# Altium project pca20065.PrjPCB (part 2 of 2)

## Sheet pca20065_switch_nx.SchDoc: =BoardTitle + ' - Switch NX'
size A3; Organization: Nordic Semiconductor; DocumentNumber: 10; Revision: 2.0.0; SheetNumber: 10; SheetTotal: 10; Author: GETR; CompanyName: Nordic Semiconductor; DrawnBy: GETR; DocumentSize: A4
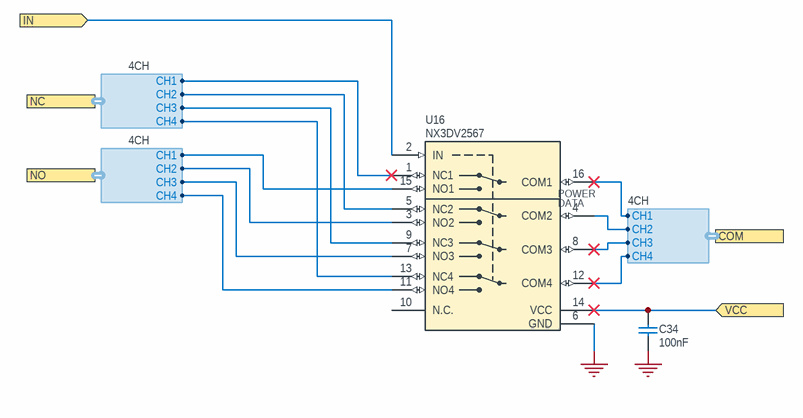
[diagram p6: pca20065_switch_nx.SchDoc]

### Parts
C34  100nF  [CAPC0603X03L_C]
U16  NX3DV2567  [XQFN40P180X260X50-16N]

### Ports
COM (harness 4CH), IN (in), NC (harness 4CH), NO (harness 4CH), VCC (in)

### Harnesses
4CH: CH1, CH2, CH3, CH4

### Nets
GND: C34.1 U16.6(GND)
4FF_1V8: U16.1(NC1) ; port NC.CH1
4FF_CLK: U16.9(NC3) ; port NC.CH3
4FF_DETECT: U16.2(IN) ; port IN
4FF_IO: U16.5(NC2) ; port NC.CH2
4FF_RST: U16.13(NC4) ; port NC.CH4
MFF_1V8: U16.15(NO1) ; port NO.CH1
MFF_CLK: U16.7(NO3) ; port NO.CH3
MFF_IO: U16.3(NO2) ; port NO.CH2
MFF_RST: U16.11(NO4) ; port NO.CH4
SIM.1V8: C34.2 U16.14(VCC) U16.16(COM1) ; port VCC, port COM.CH1
SIM.CLK: U16.8(COM3) ; port COM.CH3
SIM.IO: U16.4(COM2) ; port COM.CH2
SIM.RST: U16.12(COM4) ; port COM.CH4

Not connected (* = marked no-connect by the designer): U16 10(N.C.)

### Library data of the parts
C34 = C0201-100n: Capacitor, X5R, ±10%; Manufacturer: N.A.; Part number IPS: 00000001248, 00000002505; Part number Norautron: 262071862; Part number NEMS: 100200078; Note: 16V; Pad Count: 2; Component Status: Active
U16 = NX3DV2567GU: Low-ohmic four-pole double-throw analog switch; Manufacturer: NXP Semiconductors; Part number IPS: 00000007816; Part number NEMS: 101900290; Note: N.A.; Artikkelnr Noca: 15079317; Pad Count: 16; Component Status: Active

## Sheet pca20065_power_supply.SchDoc: =BoardTitle + ' - Power Supply'
size A3; Organization: Nordic Semiconductor; DocumentNumber: 7; Revision: 2.0.0; SheetNumber: 7; SheetTotal: 10; Author: GETR; CompanyName: Nordic Semiconductor; DrawnBy: GETR; DocumentSize: A3
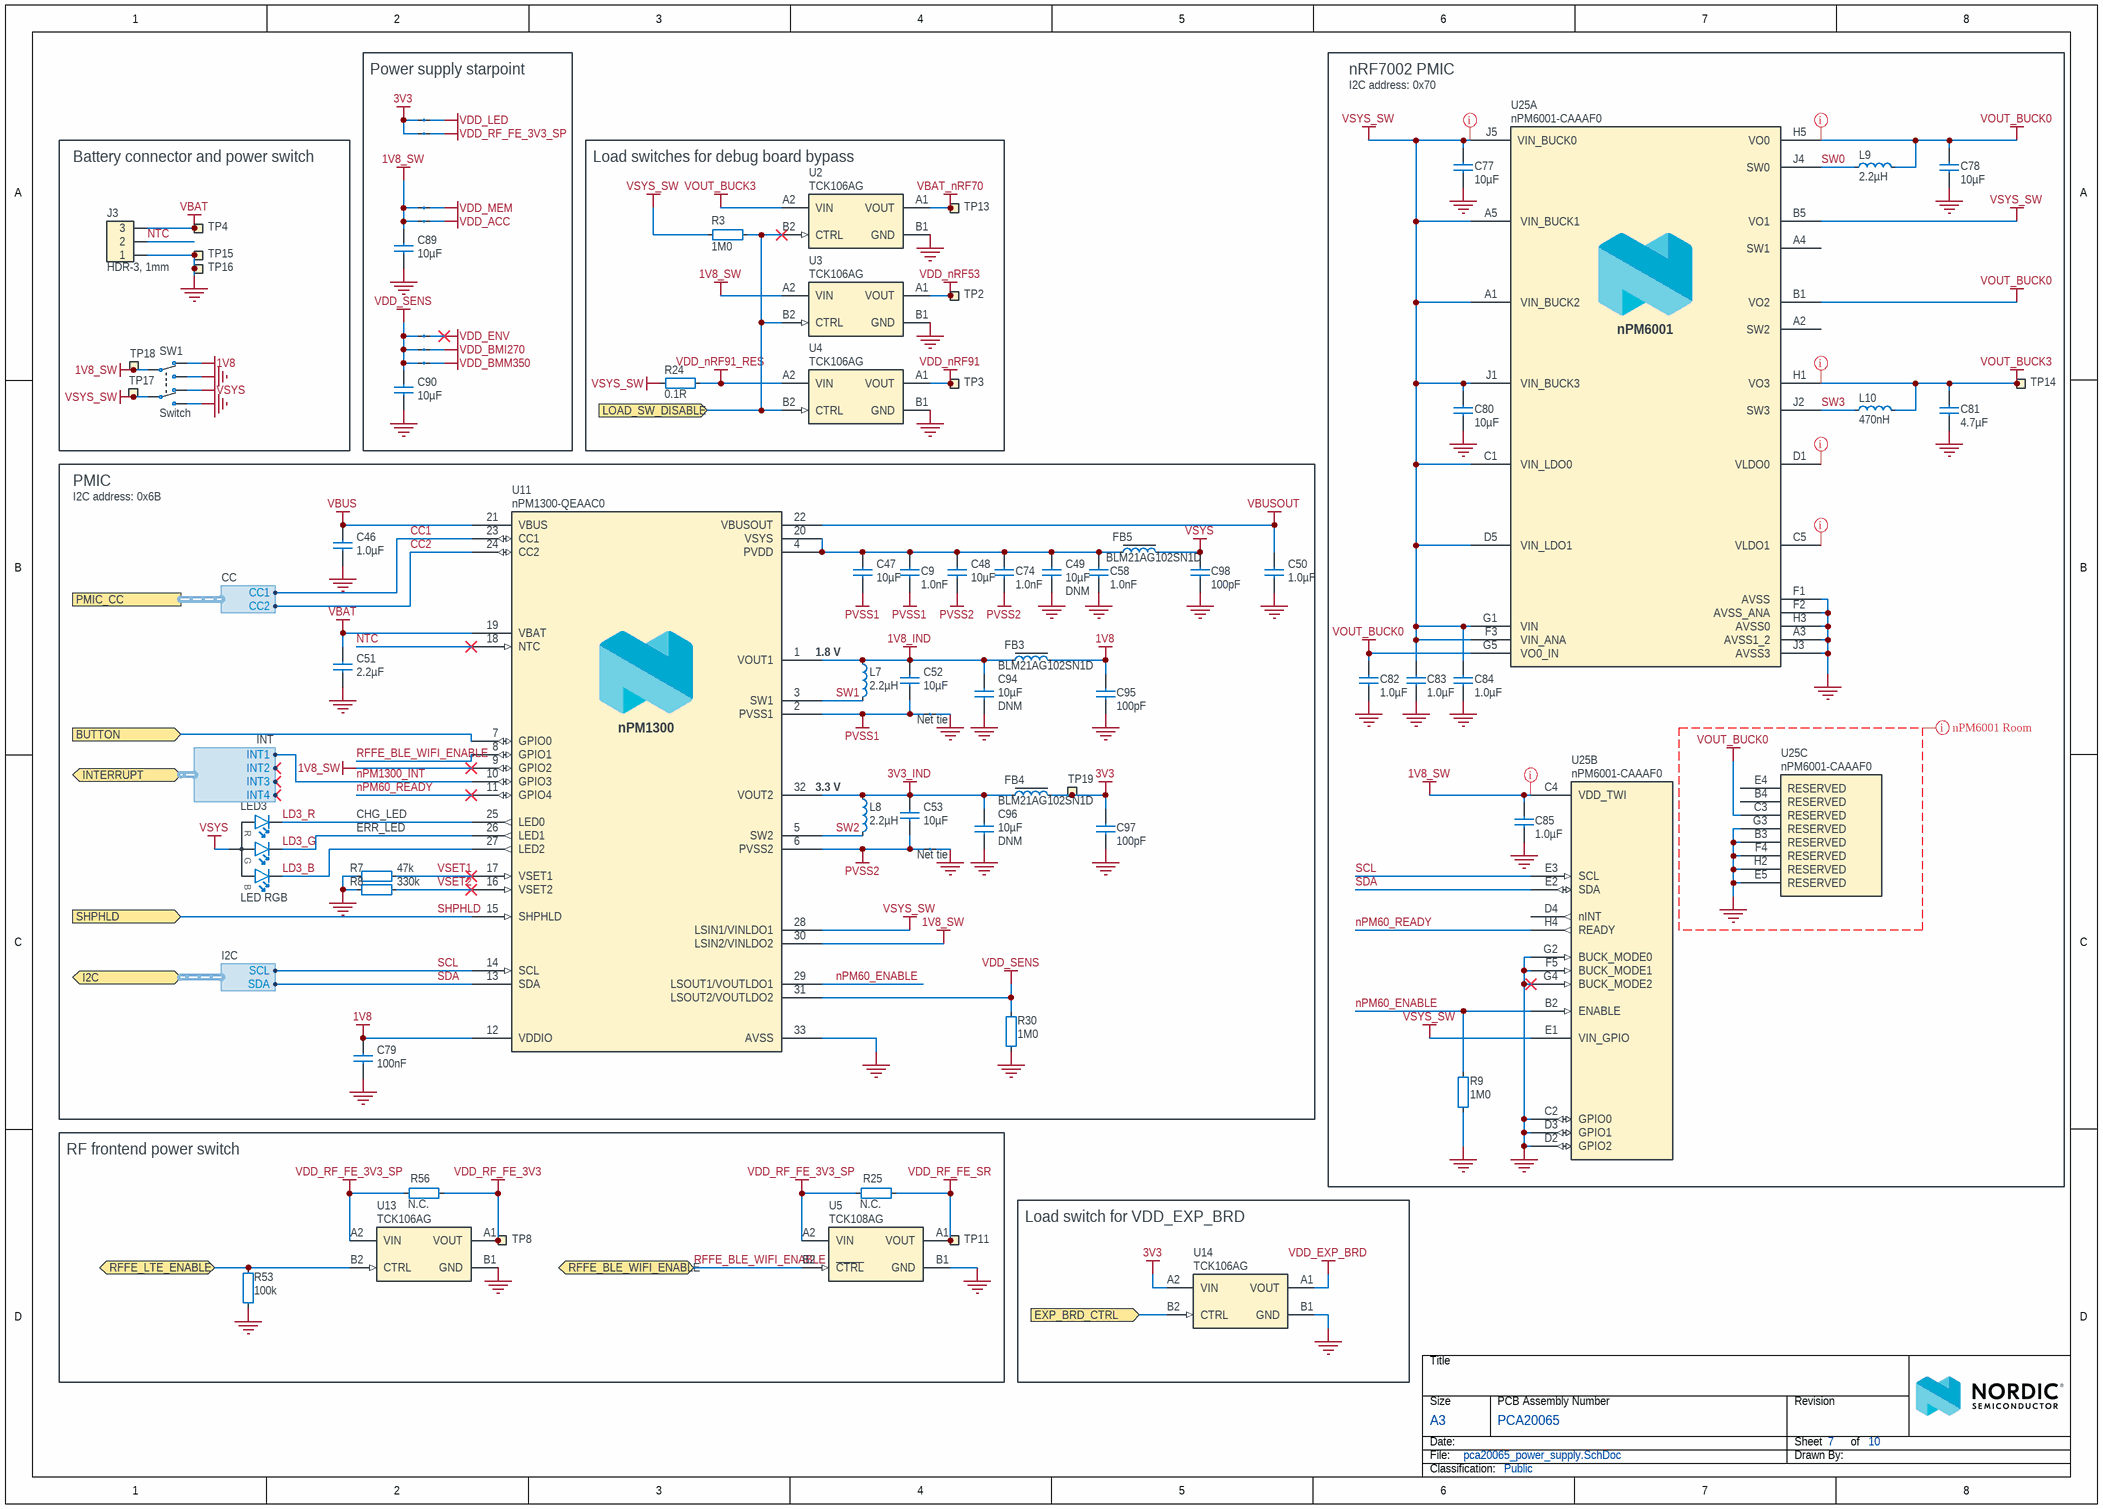
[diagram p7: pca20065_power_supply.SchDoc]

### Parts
C9  1.0nF  [CAPC0603X03L_C]
C46  1.0µF  [CAPC1608X06L]
C47  10µF  [CAPC1608X06L]
C48  10µF  [CAPC1608X06L]
C49  10µF  Assembly: DNM  [CAPC1608X06L]
C50  1.0µF  [CAPC1608X06L]
C51  2.2µF  [CAPC1608X06L]
C52  10µF  [CAPC1005X04L]
C53  10µF  [CAPC1608X06L]
C58  1.0nF  [CAPC0603X03L_C]
C74  1.0nF  [CAPC0603X03L_C]
C77  10µF  [CAPC1608X06L]
C78  10µF  [CAPC1608X06L]
C79  100nF  [CAPC0603X03L_C]
C80  10µF  [CAPC1608X06L]
C81  4.7µF  [CAPC1608X06L]
C82  1.0µF  [CAPC0603X03L_C]
C83  1.0µF  [CAPC0603X03L_C]
C84  1.0µF  [CAPC0603X03L_C]
C85  1.0µF  [CAPC0603X03L_C]
C89  10µF  [CAPC1608X06L]
C90  10µF  [CAPC1608X06L]
C94  10µF  Assembly: DNM  [CAPC1608X06L]
C95  100pF  [CAPC1005X04L]
C96  10µF  Assembly: DNM  [CAPC1608X06L]
C97  100pF  [CAPC1005X04L]
C98  100pF  [CAPC1005X04L]
FB3  BLM21AG102SN1D  [INDC2012X11L]
FB4  BLM21AG102SN1D  [INDC2012X11L]
FB5  BLM21AG102SN1D  [INDC2012X11L]
J3  HDR-3, 1mm  [SM03B-SRSS-TB]
L7  2.2µH  [INDC2016X10N]
L8  2.2µH  [INDC2016X10N]
L9  2.2µH  [INDC2016X10N]
L10  470nH  [INDC1608X06L]
LED3  LED RGB  [OVSRRGBCC3_Side]
NT1  Net tie  [2 PIN STARPOINT]  (net tie, no BOM)
NT2  Net tie  [2 PIN STARPOINT]  (net tie, no BOM)
R3  1M0  [RESC0603X03L_C]
R7  47k  [RESC0603X03L_C]
R8  330k  [RESC0603X03L_C]
R9  1M0  [RESC0603X03L_C]
R24  0.1R  [RESC1005X04L]
R25  N.C.  [RESC0603X03L_C_NC]
R30  1M0  [RESC0603X03L_C]
R53  100k  [RESC0603X03L_C]
R56  N.C.  [RESC0603X03L_C_NC]
ST1  Net tie  [2 PIN STARPOINT]  (value not drawn)  (net tie, no BOM)
ST2  Net tie  [2 PIN STARPOINT]  (value not drawn)  (net tie, no BOM)
ST3  Net tie  [2 PIN STARPOINT]  (value not drawn)  (net tie, no BOM)
ST4  Net tie  [2 PIN STARPOINT]  (value not drawn)  (net tie, no BOM)
ST5  Net tie  [2 PIN STARPOINT]  (value not drawn)  (net tie, no BOM)
ST7  Net tie  [2 PIN STARPOINT]  (value not drawn)  (net tie, no BOM)
ST9  Net tie  [2 PIN STARPOINT]  (value not drawn)  (net tie, no BOM)
SW1  Switch  [JS102011JAQN]
TP2  Ø1.5mm,SMD  [TP_SMD_D1.5mm]  (value not drawn)  (no BOM)
TP3  Ø1.5mm,SMD  [TP_SMD_D1.5mm]  (value not drawn)  (no BOM)
TP4  Ø1.5mm,SMD  [TP_SMD_D1.5mm]  (value not drawn)  (no BOM)
TP8  Ø1.0mm,SMD  [TP_SMD_D1.0mm]  (value not drawn)  (no BOM)
TP11  Ø1.0mm,SMD  [TP_SMD_D1.0mm]  (value not drawn)  (no BOM)
TP13  Ø1.5mm,SMD  [TP_SMD_D1.5mm]  (value not drawn)  (no BOM)
TP14  Ø1.5mm,SMD  [TP_SMD_D1.5mm]  (value not drawn)  (no BOM)
TP15  Ø1.5mm,SMD  [TP_SMD_D1.5mm]  (value not drawn)  (no BOM)
TP16  Ø1.5mm,SMD  [TP_SMD_D1.5mm]  (value not drawn)  (no BOM)
TP17  Ø1.5mm,SMD  [TP_SMD_D1.5mm]  (value not drawn)  (no BOM)
TP18  Ø1.5mm,SMD  [TP_SMD_D1.5mm]  (value not drawn)  (no BOM)
TP19  Ø1.5mm,SMD  [TP_SMD_D1.5mm]  (value not drawn)  (no BOM)
U2  TCK106AG  [BGA4C40P2X2_76X76X62]
U3  TCK106AG  [BGA4C40P2X2_76X76X62]
U4  TCK106AG  [BGA4C40P2X2_76X76X62]
U5  TCK108AG  [BGA4C40P2X2_76X76X62]
U11  nPM1300-QEAAC0  [Nordic_QFN50P500X500X90-33N]
U13  TCK106AG  [BGA4C40P2X2_76X76X62]
U14  TCK106AG  [BGA4C40P2X2_76X76X62]
U25  nPM6001-CAAAF0  [BGA45C40P5X9_217X364X49]  (parts A,B,C of 3)

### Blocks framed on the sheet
Power supply starpoint: C89 C90 ST1-ST5 ST7 ST9
nRF7002 PMIC: C77 C78 C80-C85 L9 L10 R9 TP14 U25
Battery connector and power switch: J3 SW1 TP4 TP15-TP18
Load switches for debug board bypass: R3 R24 TP2 TP3 TP13 U2-U4
PMIC: C9 C46-C53 C58 C74 C79 C94-C98 FB3-FB5 L7 L8 LED3 NT1 NT2 R7 R8 R30 TP19 U11
RF frontend power switch: R25 R53 R56 TP8 TP11 U5 U13
Load switch for VDD_EXP_BRD: U14

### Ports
BUTTON (in), EXP_BRD_CTRL (in), I2C (bidir, harness I2C), INTERRUPT (bidir, harness INT), LOAD_SW_DISABLE (in), PMIC_CC (harness CC), RFFE_BLE_WIFI_ENABLE (bidir), RFFE_LTE_ENABLE (bidir), SHPHLD (in)

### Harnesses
I2C: SDA, SCL
CC: CC2, CC1
INT: INT2, INT3, INT1, INT4

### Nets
1V8: C79.1 C95.2 FB3.2 SW1.3(N.C-1) U11.12(VDDIO)
1V8_IND: C52.2 C94.2 FB3.1 L7.1 U11.1(VOUT1)
1V8_SW: C85.1 C89.2 ST7.1 ST9.1 SW1.2(COM-1) TP18.1 U3.A2(VIN) U11.9(GPIO2) U11.30(LSIN2/VINLDO2) U25.C4(VDD_TWI)
3V3: C97.2 FB4.2 ST2.1 ST3.1 TP19.1 U14.A2(VIN)
3V3_IND: C53.2 C96.2 FB4.1 L8.1 U11.32(VOUT2)
GND: C46.1 C49.1 C50.1 C51.1 C58.1 C77.1 C78.1 C79.2 C80.1 C81.1 C82.2 C83.2 C84.2 C85.2 C89.1 C90.1 C94.1 C95.1 C96.1 C97.1 C98.1 J3.1 NT1.1 NT2.1 R7.2 R8.2 R9.1 R30.1 R53.1 SW1.1(N.O-1) SW1.4(N.O-2) TP15.1 TP16.1 U2.B1(GND) U3.B1(GND) U4.B1(GND) U5.B1(GND) U11.33(AVSS) U13.B1(GND) U14.B1(GND) U25.A3(AVSS1_2) U25.B3(RESERVED) U25.C2(GPIO0) U25.D2(GPIO2) U25.D3(GPIO1) U25.E5(RESERVED) U25.F1(AVSS) U25.F2(AVSS_ANA) U25.F4(RESERVED) U25.F5(BUCK_MODE1) U25.G2(BUCK_MODE0) U25.G3(RESERVED) U25.G4(BUCK_MODE2) U25.H2(RESERVED) U25.H3(AVSS0) U25.J3(AVSS3)
PVSS1: C9.1 C47.1 C52.1 NT1.2 U11.2(PVSS1)
PVSS2: C48.1 C53.1 C74.1 NT2.2 U11.6(PVSS2)
VBAT: C51.2 J3.3 TP4.1 U11.19(VBAT)
VBAT_nRF70: TP13.1 U2.A1(VOUT)
VBUS: C46.2 U11.21(VBUS)
VBUSOUT: C50.2 U11.22(VBUSOUT)
VDD_ACC: ST7.2
VDD_BMI270: ST1.2
VDD_BMM350: ST4.2
VDD_ENV: ST5.2
VDD_EXP_BRD: U14.A1(VOUT)
VDD_LED: ST2.2
VDD_MEM: ST9.2
VDD_nRF53: TP2.1 U3.A1(VOUT)
VDD_nRF91: TP3.1 U4.A1(VOUT)
VDD_nRF91_RES: R24.1 U4.A2(VIN)
VDD_RF_FE_3V3: R56.1 TP8.1 U13.A1(VOUT)
VDD_RF_FE_3V3_SP: R25.2 R56.2 ST3.2 U5.A2(VIN) U13.A2(VIN)
VDD_RF_FE_SR: R25.1 TP11.1 U5.A1(VOUT)
VDD_SENS: C90.2 R30.2 ST1.1 ST4.1 ST5.1 U11.31(LSOUT2/VOUTLDO2)
VOUT_BUCK0: C78.2 C82.1 L9.2 U25.B1(VO2) U25.C3(RESERVED) U25.G5(VO0_IN) U25.H5(VO0)
VOUT_BUCK3: C81.2 L10.2 TP14.1 U2.A2(VIN) U25.H1(VO3)
VSYS: C98.2 FB5.2 LED3.4(A) SW1.6(N.C-2)
VSYS_SW: C77.2 C80.2 C83.1 C84.1 R3.2 R24.2 SW1.5(COM-2) TP17.1 U11.28(LSIN1/VINLDO1) U25.A1(VIN_BUCK2) U25.A5(VIN_BUCK1) U25.B5(VO1) U25.C1(VIN_LDO0) U25.D5(VIN_LDO1) U25.E1(VIN_GPIO) U25.F3(VIN_ANA) U25.G1(VIN) U25.J1(VIN_BUCK3) U25.J5(VIN_BUCK0)
CC1: U11.23(CC1) ; port PMIC_CC.CC1
CC2: U11.24(CC2) ; port PMIC_CC.CC2
LD3_B: LED3.3(C_BLUE) U11.27(LED2)
LD3_G: LED3.2(C_GREEN) U11.26(LED1)
LD3_R: LED3.1(C_RED) U11.25(LED0)
LTE_BLE_COEX: R53.2 U13.B2(CTRL) ; port RFFE_LTE_ENABLE
nPM60_ENABLE: R9.2 U11.29(LSOUT1/VOUTLDO1) U25.B2(ENABLE)
nPM60_READY: U11.11(GPIO4) U25.H4(READY)
nPM1300_INT: U11.10(GPIO3) ; port INTERRUPT.INT1
NTC: J3.2 U11.18(NTC)
RFFE_BLE_WIFI_ENABLE: U5.B2(~{CTRL}) U11.8(GPIO1) ; port RFFE_BLE_WIFI_ENABLE
SCL: U11.14(SCL) U25.E3(SCL) ; port I2C.SCL
SDA: U11.13(SDA) U25.E2(SDA) ; port I2C.SDA
SHPHLD: U11.15(SHPHLD) ; port SHPHLD
SW0: L9.1 U25.J4(SW0)
SW1: L7.2 U11.3(SW1)
SW2: L8.2 U11.5(SW2)
SW3: L10.1 U25.J2(SW3)
VSET1: R7.1 U11.17(VSET1)
VSET2: R8.1 U11.16(VSET2)
NetC9_2: C9.2 C47.2 C48.2 C49.2 C58.2 C74.2 FB5.1 U11.4(PVDD) U11.20(VSYS)
NetM1_44: U11.7(GPIO0) ; port BUTTON
NetM1_59: U14.B2(CTRL) ; port EXP_BRD_CTRL
NetP9_10: R3.1 U2.B2(CTRL) U3.B2(CTRL) U4.B2(CTRL) ; port LOAD_SW_DISABLE

Not connected (* = marked no-connect by the designer): U25 A2(SW2) A4(SW1) B4(RESERVED) C5(VLDO1) D1(VLDO0) D4(nINT) E4(RESERVED)

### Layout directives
net class POWER: 1V8_SW, NetU25_C5, NetU25_D1, VOUT_BUCK0, VOUT_BUCK3, VSYS_SW
CompClassName: nPM6001: GND, VOUT_BUCK0

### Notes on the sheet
- I2C address: 0x70
- I2C address: 0x6B
- (near L7) 1.8 V
- CHG_LED
- ERR_LED
- (near L8) 3.3 V

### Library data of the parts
C9 C58 C74 = C0201-1n0: Capacitor, X7R, ±10%, 25V; Manufacturer: N.A.; Part number IPS: 00000003206; Part number NEMS: 100200056; Component Status: Active; Pad Count: 2; Note: 16V
C46 C50 = C0603-1µ0-10V-X5R: Capacitor, Ceramic, 1.0µF 10V X5R 0603,±10%; Manufacturer: N.A.; Part number NEMS: 100200528; Pad Count: 2; Component Status: Active
C47 C48 C53 C89 C90 = C0603-10µ: Capacitor, X5R, ±20%; Manufacturer: N.A.; Part number IPS: 00000007785; Part number NEMS: 100200275; Note: 6.3V; Artikkelnr Noca: 20039234; Pad Count: 2; Component Status: Active
C49 = C0603-10µ-25V-X5R-CL10A106MA8NRNC: Capacitor, X5R, ±20%, 25V; Manufacturer: Samsung Electro-Mechanics America; Part number IPS: 00000009948; Part number Norautron: N.A.; Part number NEMS: 100200354; Artikkelnr Noca: 20039436; Pad Count: 2; Component Status: Active
C51 = C0603-2.2µ-16V-X7R: Capacitor, Ceramic, X7R, ±10%, 16V; Manufacturer: Taiyo Yuden; Manufacturer Part Number: EMK107BB7225KA-T; Part number NEMS: 100200439; Component Status: Active; Pad Count: 2; Artikkelnr Noca: N.A.
C52 = C0402-10µF-6.3V-X5R-M: Multilayer Ceramic Capacitors MLCC - SMD/SMT 0402 6.3VDC 4.7uF 20% X6S; Manufacturer: Taiyo Yuden; Manufacturer Part Number: JMK105CBJ106MV-F; Part number NEMS: 100200467; Note: 6.3V; Artikkelnr Noca: N.A.; Pad Count: 2; Component Status: Active
C77 C78 C80 = C0603-10µ-10V-X7T-GRM188D71A106MA73: Capacitor, X7T, ±20%, 10V; Manufacturer: Murata; Manufacturer Part Number: GRM188D71A106MA73D; Part number IPS: 00000004696; Part number NEMS: 100200414; Pad Count: 2; Component Status: Active; Note: 10VDC; Artikkelnr Noca: N.A.
C79 = C0201-100n: Capacitor, X5R, ±10%; Manufacturer: N.A.; Part number IPS: 00000001248, 00000002505; Part number Norautron: 262071862; Part number NEMS: 100200078; Pad Count: 2; Note: 16V; Component Status: Active
C81 = C0603-4µ7: Capacitor, X5R, ±10%, 6.3V; Manufacturer: N.A.; Part number IPS: 00000007783; Part number NEMS: 100200274; Pad Count: 2; Component Status: Active; Artikkelnr Noca: 20069060
C82-C85 = C0201-1µ0: Capacitor, X5R, ±10%; Manufacturer: N.A.; Part number IPS: 00000001723; Part number NEMS: 100200084; Pad Count: 2; Component Status: Active; Note: 10V
C94 C96 = C0603-10µ-25V-X5R-CL10A106MA8NRNC: Capacitor, X5R, ±20%, 25V; Manufacturer: Samsung Electro-Mechanics America; Part number IPS: 00000009948; Part number Norautron: N.A.; Part number NEMS: 100200354; Component Status: Active; Pad Count: 2; Artikkelnr Noca: 20039436
C95 C97 C98 = C0402-100p-50V-GRM1555C1H101GA01D: Capacitor, NP0, ±2%, 50V; Manufacturer: Murata; Component Status: Active; Pad Count: 2; Artikkelnr Noca: N.A.
FB3-FB5 = FB0805-1k@100MHz-500mA: Ferrite Bead, 1k Ohm @ 100MHz, 500mA, 280 mOhm Max; Manufacturer: Murata; Part number NEMS: 100300399; Component Status: Active; Pad Count: 2; Note: Inductor Type Chip Ferrite Bead; Artikkelnr Noca: N.A.
J3 = A1002WR-S-3P-LCP: 1.0mm pitch connector side entry SMD; Manufacturer: CJT; Part number NEMS: 100500605; Note: N.A.; Pad Count: 3; Component Status: Active
L7 L8 = L0806-2µ2-2500mA-73mOhm-CIGT201610EH2R2MNE: Inductor, Irms=2.5A, Isat=2.9A, ±20%, DCR=73mΩ; Manufacturer: Samsung Electro-Mechanics America; Part number Norautron: 26521789; Part number NEMS: 100300400; Pad Count: 2; Note: Unshielded Thin Film Inductor; Artikkelnr Noca: N.A.; Component Status: Active
L9 = L0806-2µ2-2500mA-73mOhm-CIGT201610EH2R2MNE: Inductor, Irms=2.5A, Isat=2.9A, ±20%, DCR=73mΩ; Manufacturer: Samsung Electro-Mechanics America; Part number Norautron: 26521789; Part number NEMS: 100300400; Pad Count: 2; Component Status: Active; Note: Unshielded Thin Film Inductor; Artikkelnr Noca: N.A.
L10 = L0603-470n-1600mA-69mOhm-MCFK1608TR47M: Inductor, Irms=1.6A, Isat=1.9A, ±20%, DCR=69mΩ; Manufacturer: Taiyo Yuden; Part number NEMS: 100300402; Pad Count: 2; Component Status: Active; Note: -40°C ~ 125°C; Artikkelnr Noca: N.A.
LED3 = OVSRRGBCC3_Side: Optek, Side mounted RGB 1204 SMD LED; Part number NEMS: 101400026; Pad Count: 4; Artikkelnr Noca: N.A.; Component Status: Active
NT1 NT2 ST2 ST3 ST5 = 2 pin starpoint: Starpoint; Manufacturer: N.A.; Part number NEMS: 100500603; Pad Count: 2; Component Status: Active; System: Connector
R3 R9 R30 = R0201-1M0: Resistor, ±1%, 0.05W; Manufacturer: N.A.; Part number IPS: 00000001418; Part number Norautron: 26107108; Part number NEMS: 100100093; Note: Chip Res 1%; Pad Count: 2; Component Status: Active
R7 = R0201-47k: Resistor, ±1%, 0.05W; Manufacturer: N.A.; Part number IPS: 00000001423; Part number NEMS: 100100076; Component Status: Active; Pad Count: 2; Note: Chip Res 1%
R8 = R0201-330k: Resistor, ±1%, 0.05W; Manufacturer: N.A.; Part number IPS: 00000001424; Part number NEMS: 100100087; Component Status: Active; Pad Count: 2; Note: Chip Res 1%
R24 = R0402-0R1: Resistor, ±1%, 0.063W; Manufacturer: N.A.; Part number IPS: 00000001795; Part number NEMS: 100100111; Note: Chip Res 1%; Pad Count: 2; Component Status: Active
R25 R56 = R0201-N.C.: Not mounted; Manufacturer: N.A.; Part number NEMS: 100100107; Assembly: Not mounted; Note: Chip Res; Pad Count: 2; Component Status: Active
R53 = R0201-100k: Resistor, ±1%, 0.05W; Manufacturer: N.A.; Part number IPS: 00000001419; Part number Norautron: 26108487; Part number NEMS: 100100080; Note: Chip Res 1%; Pad Count: 2; Component Status: Active
ST1 ST4 ST7 ST9 = 2 pin starpoint: Starpoint; Manufacturer: N.A.; Part number NEMS: 100500603; Component Status: Active; Pad Count: 2; System: Connector
SW1 = Switch-Slide-RA-J-Lead-DPDT-8.5x3.5mm_C&K: SMD slide Switch (ON-ON); Manufacturer: C&K; Manufacturer Part Number: JS202011JAQN; Part number IPS: 00000007811; Part number NEMS: 101500037; Note: N.A.; Pad Count: 6; Component Status: Active
TP2-TP4 TP13-TP19 = TP_SMD_Ø1.5MM: 1.5mm circular SMD testpad; Manufacturer: Nordic Semiconductor; Manufacturer Part Number: N.A.; Part number NEMS: 100500477; Pad Count: 1; Component Status: Active
TP8 TP11 = TP_SMD_Ø1.0MM: 1.0mm circular SMD testpad; Manufacturer: Nordic Semiconductor; Manufacturer Part Number: N.A.; Part number NEMS: 100500475; Pad Count: 1; Component Status: Active
U2-U4 U14 = TCK106AG: 1.0 A Load Switch IC with Slew Rate Control Driver in Ultra Small Package; Manufacturer: Toshiba; Manufacturer Part Number: TCK106AG,LF; Part number IPS: 00000004390; Part number Norautron: 26500627; Part number NEMS: 101900575; Note: N.A.; Pad Count: 4; Component Status: Active
U5 = TCK108AG: 1.0 A Load Switch IC with Slew Rate Control Driver in Ultra Small Package; Manufacturer: Toshiba; Manufacturer Part Number: TCK108AG,LF; Part number NEMS: 101900814; Pad Count: 4; Note: N.A.; Component Status: Active
U11 = nPM1300-QEAAC0: Li-Ion/Li-Polymer USB-C battery charger with high efficiency buck regulators, LDOs or load switches, LED drivers, TWI and VBUSOUT; Manufacturer: Nordic Semiconductor; Part number NEMS: 102000306; Component Status: Active; Pad Count: 33; Note: Production version; Artikkelnr Noca: N.A.
U13 = TCK106AG: 1.0 A Load Switch IC with Slew Rate Control Driver in Ultra Small Package; Manufacturer: Toshiba; Manufacturer Part Number: TCK106AG,LF; Part number IPS: 00000004390; Part number Norautron: 26500627; Part number NEMS: 101900575; Pad Count: 4; Note: N.A.; Component Status: Active
U25 = nPM6001-CAAAF0: Low-power and high efficiency PMIC; Manufacturer: Nordic Semiconductor; Part number NEMS: 102000358; Component Status: Active; Pad Count: 45; Note: N.A.

## Sheet pca20065_rf_front-end.SchDoc: =BoardTitle + ' - RF FE'
size A3; Organization: Nordic Semiconductor; DocumentNumber: 5; Revision: 2.0.0; SheetNumber: 5; SheetTotal: 10; Author: GETR; CompanyName: Nordic Semiconductor; DrawnBy: GETR; DocumentSize: A3
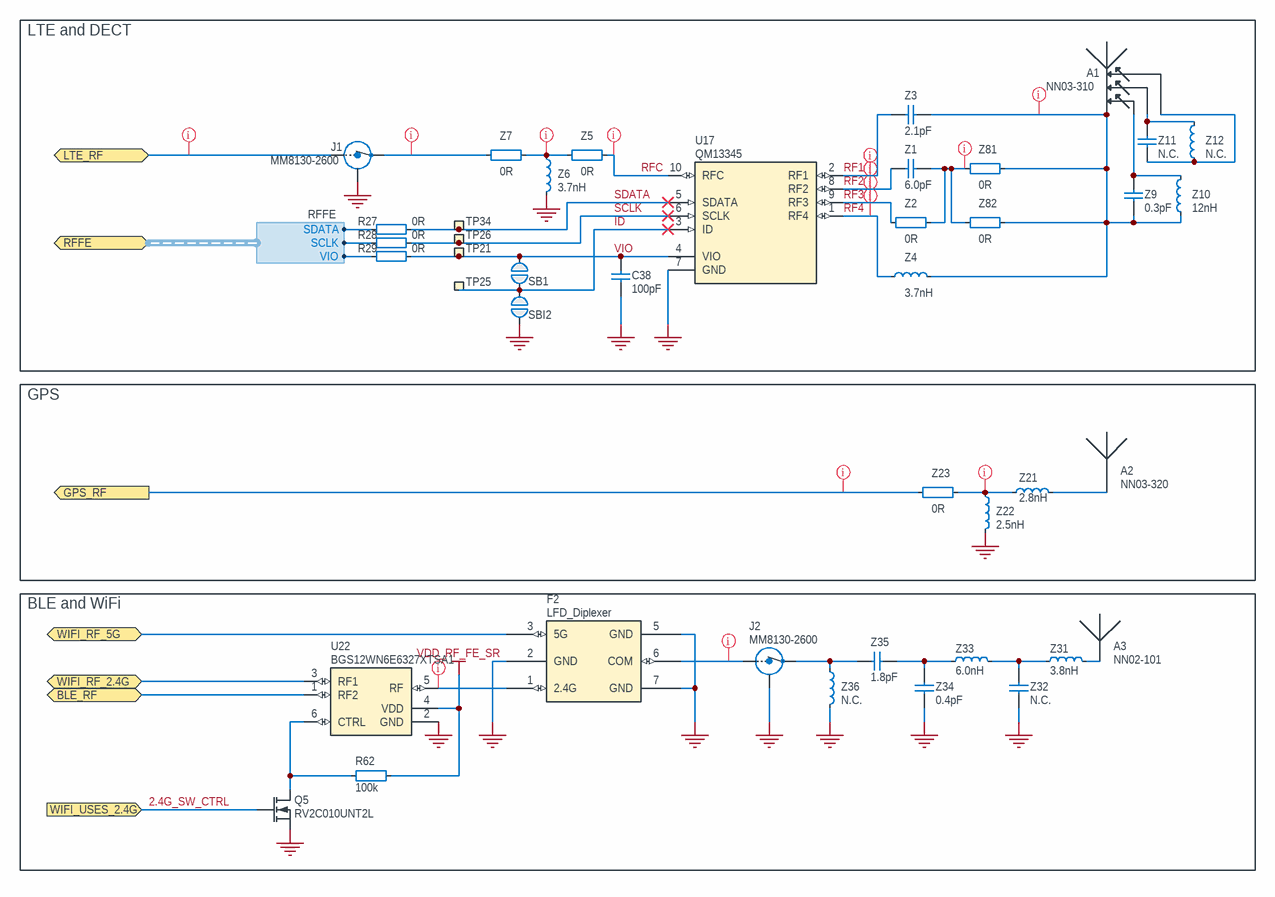
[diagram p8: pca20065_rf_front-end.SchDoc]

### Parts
A1  NN03-310  [NN03-310_RF_ALT1]
A2  NN03-320  [NN03-320]
A3  NN02-101  [NN02-101_Corner]
C38  100pF  [CAPC0603X03L_C]
F2  LFD_Diplexer  [CAF-50P160X80-6N]
J1  MM8130-2600  [COAXIAL-SWF]
J2  MM8130-2600  [COAXIAL-SWF]
Q5  RV2C010UNT2L  [DFN65P100X40-3L]
R27  0R  [RESC0603X03L_C]
R28  0R  [RESC0603X03L_C]
R29  0R  [RESC0603X03L_C]
R62  100k  [RESC0603X03L_C]
SB1  Solderbridge  [Solderbridge]  (value not drawn)  (no BOM)
SBI2  Solderbridge  [Solderbridge]  (value not drawn)  (no BOM)
TP21  Ø1.0mm,SMD  [TP_SMD_D1.0mm]  (value not drawn)  (no BOM)
TP25  Ø1.0mm,SMD  [TP_SMD_D1.0mm]  (value not drawn)  (no BOM)
TP26  Ø1.0mm,SMD  [TP_SMD_D1.0mm]  (value not drawn)  (no BOM)
TP34  Ø1.0mm,SMD  [TP_SMD_D1.0mm]  (value not drawn)  (no BOM)
U17  QM13345  [PQFN40P110X150X50-10N]
U22  value BGS12WN6E6327XTSA1  [TSNP-6-8]  (hidden comment: BGS12xN6)
Z1  6.0pF  [C1608X06L-C1005X04M]
Z2  0R  [C1608X06L-C1005X04M]
Z3  2.1pF  [C1608X06L-C1005X04M]
Z4  3.7nH  [C1608X06L-C1005X04M]
Z5  0R  [C1608X06L-C1005X04M]
Z6  3.7nH  [C1608X06L-C1005X04M]
Z7  0R  [C1608X06L-C1005X04M]
Z9  0.3pF  [C1608X06L-C1005X04M]
Z10  12nH  [C1608X06L-C1005X04M]
Z11  N.C.  [C1608X06L-C1005X04M]
Z12  N.C.  [C1608X06L-C1005X04M]
Z21  2.8nH  [C1608X06L-C1005X04M]
Z22  2.5nH  [C1608X06L-C1005X04M]
Z23  0R  [C1608X06L-C1005X04M]
Z31  3.8nH  [C1608X06L-C1005X04M]
Z32  N.C.  [C1608X06L-C1005X04M]
Z33  6.0nH  [C1608X06L-C1005X04M]
Z34  0.4pF  [C1608X06L-C1005X04M]
Z35  1.8pF  [C1608X06L-C1005X04M]
Z36  N.C.  [C1608X06L-C1005X04M]
Z81  0R  [C1608X06L-C1005X04M]
Z82  0R  [C1608X06L-C1005X04M]

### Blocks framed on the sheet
LTE and DECT: A1 C38 J1 R27-R29 SB1 SBI2 TP21 TP25 TP26 TP34 U17 Z1-Z7 Z9-Z12 Z81 Z82
GPS: A2 Z21-Z23
BLE and WiFi: A3 F2 J2 Q5 R62 U22 Z31-Z36

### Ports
BLE_RF (bidir), GPS_RF (out), LTE_RF (bidir), RFFE (bidir, harness RFFE), WIFI_RF_2.4G (bidir), WIFI_RF_5G (bidir), WIFI_USES_2.4G (in)

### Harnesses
RFFE: VIO, SCLK, SDATA

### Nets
GND: C38.1 F2.2(GND) F2.5(GND) F2.7(GND) J1.2(Shield) J2.2(Shield) Q5.2(S) SBI2.2 U17.7(GND) U22.2(GND) Z6.2 Z22.2 Z32.1 Z34.2 Z36.2
VDD_RF_FE_SR: R62.1 U22.4(VDD)
2.4G_SW_CTRL: Q5.1(G) ; port WIFI_USES_2.4G
ID: SB1.2 SBI2.1 TP25.1 U17.3(ID)
RF1: U17.2(RF1) Z3.1
RF2: U17.8(RF2) Z1.1
RF3: U17.9(RF3) Z2.1
RF4: U17.1(RF4) Z4.1
RFC: U17.10(RFC) Z5.2
SCLK: R28.2 TP26.1 U17.6(SCLK)
SDATA: R27.2 TP34.1 U17.5(SDATA)
VIO: C38.2 R29.2 SB1.1 TP21.1 U17.4(VIO)
NetA1_1: A1.1(Feed) Z3.2 Z4.2 Z9.1 Z10.1 Z81.2 Z82.2
NetA1_2: A1.2(Tuning) Z9.2 Z10.2
NetA1_3: A1.3(Tuning) Z11.2 Z12.2
NetA1_4: A1.4(Tuning) Z11.1 Z12.1
NetA2_4: A2.4(Feed1) Z21.2
NetA3_1: A3.1 Z31.2
NetCR1_2: U22.1(RF2) ; port BLE_RF
NetF2_1: F2.1(2.4G) U22.5(RF)
NetF2_3: F2.3(5G) ; port WIFI_RF_5G
NetF2_6: F2.6(COM) J2.1(IN)
NetJ1_1: J1.1(IN) ; port LTE_RF
NetJ1_3: J1.3(OUT) Z7.1
NetJ2_3: J2.3(OUT) Z35.1 Z36.1
NetM1_27: R27.1 ; port RFFE.SDATA
NetM1_28: R28.1 ; port RFFE.SCLK
NetM1_29: R29.1 ; port RFFE.VIO
NetQ5_3: Q5.3(D) R62.2 U22.6(CTRL)
NetU9_5: Z23.1 ; port GPS_RF
NetU21_9: U22.3(RF1) ; port WIFI_RF_2.4G
NetZ1_2: Z1.2 Z2.2 Z81.1 Z82.1
NetZ5_1: Z5.1 Z6.1 Z7.2
NetZ21_1: Z21.1 Z22.1 Z23.2
NetZ31_1: Z31.1 Z32.2 Z33.2
NetZ33_1: Z33.1 Z34.1 Z35.2

Not connected (* = marked no-connect by the designer): A2 1(NC) 2(GND) 3(Feed2); U22 8(NC)

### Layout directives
net class RF: NetA1_1, NetJ1_1, NetJ1_3, NetU9_5, NetZ1_2, NetZ5_1, NetZ21_1, RF1, RF2, RF3, RF4, RFC
net class RF_BLE/WIFI: NetF2_1, NetF2_6

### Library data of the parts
A1 = NN03-310-R: Mobile IoT LTE Multi-Band Antenna; Manufacturer: Ignion; Part number IPS: 80000001819; Part number NEMS: 100700053; Pad Count: 5; Note: N.A.; Component Status: Active
A2 = NN03-320: Dual-Band GNSS and Wi-Fi/BluetoothAntenna; Manufacturer: Ignion; Part number NEMS: 100700066; Pad Count: 4; Note: N.A.; Component Status: Active
A3 = NN02-101_Corner: Miniature and high-efficiency Bluetooth/Wi-Fi antenna; Manufacturer: Ignion; Part number NEMS: 100700077; Component Status: Active; Pad Count: 2; Note: N.A.
C38 = C0201-100p: Capacitor, NP0, ±2%, 25V; Manufacturer: Murata; Manufacturer Part Number: GRM0335C1E101GA01D; Part number IPS: 00000007853; Part number NEMS: 100200044; Pad Count: 2; Artikkelnr Noca: N.A.; Component Status: Active
F2 = LFD182G45DCJD247: Signal Conditioning 2.4GHz and 5GHz Diplexer; Manufacturer: Murata; Part number NEMS: 100800026; Pad Count: 6; Note: N.A.; Component Status: Active
J1 J2 = MM8130-2600: Coaxial Connector with Switch; Manufacturer: Murata; Part number IPS: 00000009955; Part number Norautron: 26030338; Part number NEMS: 100500400; Note: N.A.; Artikkelnr Noca: 55029011; Pad Count: 3; Component Status: Active
Q5 = RV2C010UNT2L: N-Channel MOSFET, 20V, 1A, 470mOhm, 400mW; Manufacturer: Rohm Semiconductor; Part number IPS: 00000009976; Part number Norautron: 26320026; Part number NEMS: 101300132; Note: N.A.; Artikkelnr Noca: 35010020; Pad Count: 3; Component Status: Active
R27-R29 = R0201-0R: Resistor, ±5%, 0.05W; Manufacturer: N.A.; Part number IPS: 00000003245; Part number NEMS: 100100001; Pad Count: 2; Note: Chip Res 5%; Component Status: Active
R62 = R0201-100k: as R53 on sheet pca20065_power_supply
SB1 SBI2 = Solderbridge: Manufacturer: N.A.; Part number NEMS: 100500458; Pad Count: 2; Component Status: Active; System: Connector
TP21 TP25 TP26 TP34 = TP_SMD_Ø1.0MM: 1.0mm circular SMD testpad; Manufacturer: Nordic Semiconductor; Manufacturer Part Number: N.A.; Part number NEMS: 100500475; Pad Count: 1; Component Status: Active; System: Connector
U17 = QM13345: SP4T RF Switch with RFFE Interface; Manufacturer: Qorvo; Part number NEMS: 101900679; Pad Count: 10; Note: N.A.; Component Status: Active
U22 = BGS12WN6E6327XTSA1: Wideband SPDT RF Switch, 50MHz-6GHz. Max 26dBm, 1.65-3.6V; Manufacturer: Infineon Technologies; Part number NEMS: 101900784; Component Status: Active; Pad Count: 6; Note: N.A.
Z1 = C0402-6.0p-50V-NP0-GJM1555C1H6R0WB01: Capacitor, NP0, ±0.05pF, 50V; Manufacturer: Murata; Manufacturer Part Number: GJM1555C1H6R0WB01D; Part number NEMS: 100200532; Pad Count: 2; Note: N.A.; Component Status: Active
Z2 Z5 Z7 Z23 Z81 Z82 = R0603-0r: Resistor, ±5%, 0.1W; Manufacturer: N.A.; Part number NEMS: 100100283; Pad Count: 2; Note: Chip Res 5%; Artikkelnr Noca: 27069000; Component Status: Active
Z3 = C0402-2.1p-50V-NP0-GJM1555C1H2R1WB01: Capacitor, NP0, ±0.05pF, 50V; Manufacturer: Murata; Manufacturer Part Number: GJM1555C1H2R1WB01D; Part number NEMS: 100200533; Pad Count: 2; Note: N.A.; Component Status: Active
Z4 Z6 = L0402-3n7-1950mA-30mΩ-LQW15AN3N7G80: Inductor, 1950mA, ±2%, 30mΩ, Q=35; Manufacturer: Murata; Manufacturer Part Number: LQW15AN3N7G80D; Part number NEMS: 100300421; Pad Count: 2; Note: -55°C ~ 125°C; Artikkelnr Noca: N.A.; Component Status: Active
Z9 = C0402-0.3p-HQ-Murata: Capacitor, NP0, ±0.05pF, 50V; Manufacturer: Murata; Manufacturer Part Number: GJM1555C1HR30WB01D; Part number IPS: 00000001777; Part number NEMS: 100200433; Pad Count: 2; Artikkelnr Noca: N.A.; Component Status: Active
Z10 = L0603-12n-750mA-71mΩ-LQW18AN12NG10: Inductor, 750mA, ±2%, 71mΩ, Q=38; Manufacturer: Murata; Part number NEMS: 100300414; Pad Count: 2; Note: -55°C ~ 125°C; Artikkelnr Noca: N.A.; Component Status: Active
Z11 Z32 = C0402-N.C.: Not mounted; Manufacturer: N.A.; Part number NEMS: 100200105; Pad Count: 2; Note: Chip Cap; Assembly: Not mounted; Component Status: Active
Z12 = L0402-N.C.: Not mounted; Manufacturer: N.A.; Part number NEMS: 100300037; Pad Count: 2; Assembly: Not mounted; Component Status: Active
Z21 = L0402-2n8-1500mA-47mΩ-LQW15AN2N8G80: Inductor, 1500mA, ±2%, 47mΩ, Q=27; Manufacturer: Murata; Manufacturer Part Number: LQW15AN2N8G80D; Part number NEMS: 100300422; Component Status: Active; Pad Count: 2; Note: -55°C ~ 125°C; Artikkelnr Noca: N.A.
Z22 = L0402-2n5-Wirewound-Murata-LQW15AN2N5G80: Inductor, 2100mA, ±2%, 30mΩ, Q=30; Manufacturer: Murata; Manufacturer Part Number: LQW15AN2N5G80D; Part number NEMS: 100300417; Pad Count: 2; Note: -55°C ~ 125°C; Artikkelnr Noca: N.A.; Component Status: Active
Z31 = L0402-3n8-Wirewound-Murata_HQ-LQW15AN3N8G80D: 3.8 nH Unshielded Drum Core, Wirewound Inductor 1.95 A 30mOhm Max 0402 (1005 Metric); Manufacturer: Murata; Part number NEMS: 100300486; Pad Count: 2; Note: -55°C ~ 125°C; Artikkelnr Noca: N.A.; Component Status: Active
Z33 = L0402-9n0-Wirewound-Murata_HQ-LQW15AN6N0B80D: 6 nH Unshielded Drum Core, Wirewound Inductor 1.6 A 56mOhm Max 0402 (1005 Metric); Manufacturer: Murata; Part number NEMS: 100300487; Pad Count: 2; Note: -55°C ~ 125°C; Artikkelnr Noca: N.A.; Component Status: Active
Z34 = C0402-0.4p-50V-NP0-GJM1555C1HR40WB01: Capacitor, NP0, ±0.05pF, 50V; Manufacturer: Murata; Manufacturer Part Number: GJM1555C1HR40WB01D; Part number NEMS: 100200500; Pad Count: 2; Artikkelnr Noca: N.A.; Component Status: Active
Z35 = C0402-1.8p-HQ-Murata: Capacitor, C0G, ±0.05pF, 50V; Manufacturer: Murata; Manufacturer Part Number: GJM1555C1H1R8WB01D; Part number NEMS: 100200521; Pad Count: 2; Artikkelnr Noca: N.A.; Component Status: Active
Z36 = L0603-N.C.: Not mounted; Manufacturer: N.A.; Part number NEMS: 100300069; Pad Count: 2; Assembly: Not mounted; Component Status: Active

## Sheet pca20065_nrf7002.SchDoc: =BoardTitle + ' - nRF7002'
size A3; Organization: Nordic Semiconductor; DocumentNumber: 4; Revision: 2.0.0; SheetNumber: 4; SheetTotal: 10; Author: GETR; CompanyName: Nordic Semiconductor; DrawnBy: GETR; DocumentSize: A3
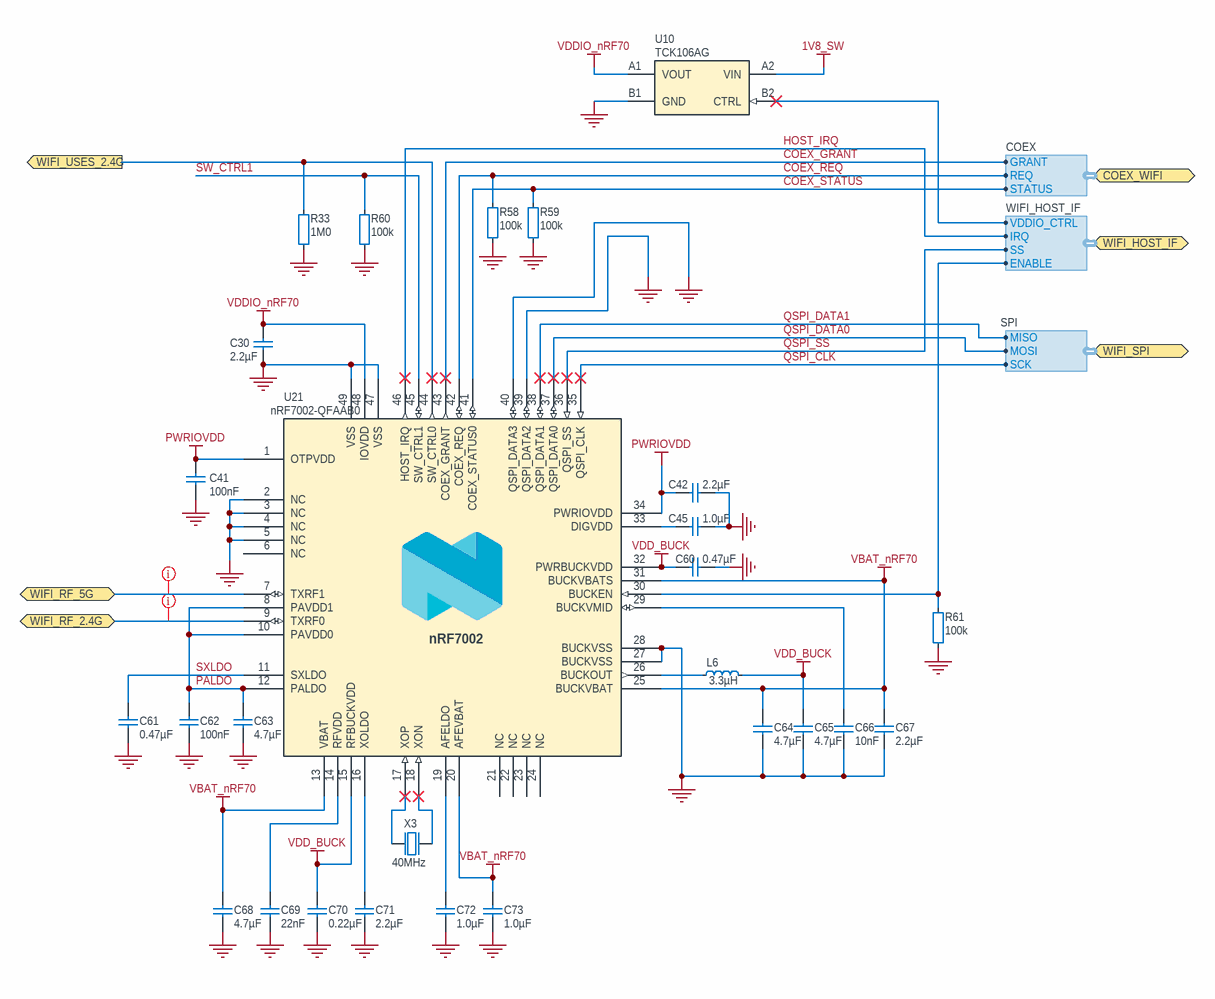
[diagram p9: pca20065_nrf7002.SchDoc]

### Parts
C30  2.2µF  [CAPC1608X06L]
C41  100nF  [CAPC0603X03L_C]
C42  2.2µF  [CAPC1005X04L]
C45  1.0µF  [CAPC1005X04L]
C60  0.47µF  [CAPC0603X03L_C]
C61  0.47µF  [CAPC0603X03L_C]
C62  100nF  [CAPC0603X03L_C]
C63  4.7µF  [CAPC1608X06L]
C64  4.7µF  [CAPC1608X06L]
C65  4.7µF  [CAPC1608X06L]
C66  10nF  [CAPC0603X03L_C]
C67  2.2µF  [CAPC1608X06L]
C68  4.7µF  [CAPC1608X06L]
C69  22nF  [CAPC0603X03L_C]
C70  0.22µF  [CAPC0603X03L_C]
C71  2.2µF  [CAPC0603X03L_C]
C72  1.0µF  [CAPC1005X04L]
C73  1.0µF  [CAPC1005X04L]
L6  3.3µH  [INDC2520X10N]
R33  1M0  [RESC0603X03L_C]
R58  100k  [RESC0603X03L_C]
R59  100k  [RESC0603X03L_C]
R60  100k  [RESC0603X03L_C]
R61  100k  [RESC0603X03L_C]
U10  TCK106AG  [BGA4C40P2X2_76X76X62]
U21  nRF7002-QFAAB0  [QFN40P600X600X60-48N]
X3  40MHz  [BT-XTAL_1612]

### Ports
COEX_WIFI (bidir, harness COEX), WIFI_HOST_IF (bidir, harness WIFI_HOST_IF), WIFI_RF_2.4G (bidir), WIFI_RF_5G (bidir), WIFI_SPI (bidir, harness SPI), WIFI_USES_2.4G (out)

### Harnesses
WIFI_HOST_IF: SS, IRQ, ENABLE, VDDIO_CTRL
COEX: STATUS, REQ, GRANT
SPI: MISO, MOSI, SCK

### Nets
1V8_SW: U10.A2(VIN)
GND: C30.1 C41.1 C42.1 C45.2 C60.1 C61.1 C62.2 C63.1 C64.1 C65.1 C66.2 C67.2 C68.1 C69.1 C70.1 C71.1 C72.1 C73.1 R33.1 R58.2 R59.2 R60.1 R61.2 U10.B1(GND) U21.2(NC) U21.3(NC) U21.4(NC) U21.5(NC) U21.27(BUCKVSS) U21.28(BUCKVSS) U21.39(QSPI_DATA2) U21.40(QSPI_DATA3) U21.47(VSS) U21.49(VSS) X3.2(GND) X3.4(GND)
PWRIOVDD: C41.2 C42.2 U21.1(OTPVDD) U21.34(PWRIOVDD)
VBAT_nRF70: C64.2 C67.1 C68.2 C73.2 U21.13(VBAT) U21.20(AFEVBAT) U21.25(BUCKVBAT) U21.31(BUCKVBATS)
VDD_BUCK: C60.2 C65.2 C70.2 L6.2 U21.15(RFBUCKVDD) U21.32(PWRBUCKVDD)
VDDIO_nRF70: C30.2 U10.A1(VOUT) U21.48(IOVDD)
2.4G_SW_CTRL: R33.2 U21.44(SW_CTRL0) ; port WIFI_USES_2.4G
BUCKEN: R61.1 U21.30(BUCKEN) ; port WIFI_HOST_IF.ENABLE
COEX_GRANT: U21.43(COEX_GRANT) ; port COEX_WIFI.GRANT
COEX_REQ: R58.1 U21.42(COEX_REQ) ; port COEX_WIFI.REQ
COEX_STATUS: R59.1 U21.41(COEX_STATUS0) ; port COEX_WIFI.STATUS
HOST_IRQ: U21.46(HOST_IRQ) ; port WIFI_HOST_IF.IRQ
PALDO: C62.1 C63.2 U21.8(PAVDD1) U21.10(PAVDD0) U21.12(PALDO)
QSPI_CLK: U21.35(QSPI_CLK) ; port WIFI_SPI.SCK
QSPI_DATA0: U21.37(QSPI_DATA0) ; port WIFI_SPI.MOSI  [project net MOSI]
QSPI_DATA1: U21.38(QSPI_DATA1) ; port WIFI_SPI.MISO  [project net MISO]
QSPI_SS: U21.36(QSPI_SS) ; port WIFI_HOST_IF.SS
SW_CTRL1: R60.2 U21.45(SW_CTRL1)
SXLDO: C61.2 U21.11(SXLDO)
VDDIO_CTRL: U10.B2(CTRL) ; port WIFI_HOST_IF.VDDIO_CTRL
NetC45_1: C45.1 U21.33(DIGVDD)
NetC66_1: C66.1 U21.29(BUCKVMID)
NetC69_2: C69.2 U21.14(RFVDD)
NetC71_2: C71.2 U21.16(XOLDO)
NetC72_2: C72.2 U21.19(AFELDO)
NetF2_3: U21.7(TXRF1) ; port WIFI_RF_5G
NetL6_1: L6.1 U21.26(BUCKOUT)
NetU21_9: U21.9(TXRF0) ; port WIFI_RF_2.4G
NetU21_17: U21.17(XOP) X3.1(inp)
NetU21_18: U21.18(XON) X3.3(out)

Not connected (* = marked no-connect by the designer): U21 6(NC) 21(NC) 22(NC) 23(NC) 24(NC)

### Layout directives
net class RF_BLE/WIFI: NetF2_3, NetU21_9

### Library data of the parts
C30 C67 = C0603-2µ2-16V-X7S-GRM188C71C225KE11: Capacitor, Ceramic, 2.2µF 16V X7S 0603,±10%; Manufacturer: Murata; Manufacturer Part Number: GRM188C71C225KE11D; Part number NEMS: 100200490; Pad Count: 2; Artikkelnr Noca: N.A.; Component Status: Active
C41 C62 = C0201-100n-16V-X7S-GRM033C71C104KE14: Capacitor, Ceramic, 100nF 16V X7S 0201,±10%; Manufacturer: Murata; Manufacturer Part Number: GRM033C71C104KE14D; Part number NEMS: 100200494; Pad Count: 2; Artikkelnr Noca: N.A.; Component Status: Active
C42 = C0402-2µ2-25V-X5R-GRM155R61E225KE11: Capacitor, Ceramic, 2.2µF 25V X5R 0402,±10%; Manufacturer: Murata; Manufacturer Part Number: GRM155R61E225KE11D; Part number NEMS: 100200492; Pad Count: 2; Artikkelnr Noca: N.A.; Component Status: Active
C45 = C0402-1µ0-16V-X6S-GRM155C81C105KE11D: Capacitor, Ceramic, 1.0µF 16V X6S 0402,±10%; Manufacturer: Murata; Part number NEMS: 100200516; Pad Count: 2; Artikkelnr Noca: N.A.; Component Status: Active
C60 C61 = C0201-470n-6.3V-X5R-GRM033R60J474KE90: Capacitor, Ceramic, 0.47µF 6.3V X5R 0201,±10%; Manufacturer: Murata; Manufacturer Part Number: GRM033R60J474KE90D; Part number NEMS: 100200488; Pad Count: 2; Artikkelnr Noca: N.A.; Component Status: Active
C63-C65 C68 = C0603-4µ7-25V-X6S-GRM188C81E475KE11: Capacitor, Ceramic, 4.7µF 25V X6S 0603,±10%; Manufacturer: Murata; Manufacturer Part Number: GRM188C81E475KE11D; Part number NEMS: 100200486; Pad Count: 2; Artikkelnr Noca: N.A.; Component Status: Active
C66 = C0201-10n-16V-X7R-GRM033R71C103KE14: Capacitor, Ceramic, 10nF 16V X7R 0201,±10%; Manufacturer: Murata; Manufacturer Part Number: GRM033R71C103KE14D; Part number NEMS: 100200491; Pad Count: 2; Artikkelnr Noca: N.A.; Component Status: Active
C69 = C0201-22n-10V-X5R-GRM033R61A223KE84: Capacitor, Ceramic, 22nF 10V X5R 0201,±10%; Manufacturer: Murata; Manufacturer Part Number: GRM033R61A223KE84D; Part number NEMS: 100200495; Pad Count: 2; Artikkelnr Noca: N.A.; Component Status: Active
C70 = C0201-220n-10V-X5R-GRM033R61A224KE90: Capacitor, Ceramic, 0.22µF 10V X5R 0201, ±10%; Manufacturer: Murata; Manufacturer Part Number: GRM033R61A224KE90D; Part number NEMS: 100200487; Pad Count: 2; Artikkelnr Noca: N.A.; Component Status: Active
C71 = C0201-2µ2-10V-X5R-GRM033R61A225KE47: Capacitor, Ceramic, 2.2µF 10V X5R 0201,±10%; Manufacturer: Murata; Manufacturer Part Number: GRM033R61A225KE47D; Part number NEMS: 100200496; Pad Count: 2; Artikkelnr Noca: N.A.; Component Status: Active
C72 = C0402-1µ0-10V-X7S-GRM155C71A105KE11: Capacitor, Ceramic, 1.0µF 10V X7S 0402,±10%; Manufacturer: Murata; Manufacturer Part Number: GRM155C71A105KE11D; Part number NEMS: 100200497; Pad Count: 2; Artikkelnr Noca: N.A.; Component Status: Active
C73 = C0402-1µ0-35V-X5R-GRM155R6YA105KE11: Capacitor, Ceramic, 1.0µF 35V X5R 0402,±10%; Manufacturer: Murata; Manufacturer Part Number: GRM155R6YA105KE11D; Part number NEMS: 100200489; Pad Count: 2; Artikkelnr Noca: N.A.; Component Status: Active
L6 = L1008-3µ3-LQM2HPN3R3MGCL: Inductor, 1A, ±20%, 200mOhm; Manufacturer: Murata; Part number NEMS: 100300406; Pad Count: 2; Note: -55°C ~ 125°C; Artikkelnr Noca: N.A.; Component Status: Active
R33 = R0201-1M0: as R3 on sheet pca20065_power_supply
R58-R61 = R0201-100k: as R53 on sheet pca20065_power_supply
U10 = TCK106AG: as U2 on sheet pca20065_power_supply
U21 = nRF7002-QFAAB0: Wi-fi Dual Band Companion chip; Manufacturer: Nordic Semiconductor; Part number NEMS: 102000276; Pad Count: 49; Note: N.A.; Component Status: Active
X3 = XTAL_SMD1612_40MHz_8pF: XTAL SMD 1612, 40MHz, Cl=8pF, Total Tol: ±10ppm; Manufacturer: Abracon Corporation; Manufacturer Part Number: ABM12W-40.0000MHZ-8-B1U-T3; Part number NEMS: 101600095; Pad Count: 4; Note: XTAL SMD 40.000MHz 8pF; Artikkelnr Noca: N.A.; Component Status: Active

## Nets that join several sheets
1V8_SW: pca20065_nrf9151 (C4.1 C5.1 M1.65 R106.1), pca20065_sensors_and_leds (9 pins), pca20065_interface (8 pins), pca20065_switch_fsa (C55.1 U12.14), pca20065_power_supply (10 pins), pca20065_nrf7002 (U10.A2)
3V3: pca20065_interface (P9.14), pca20065_power_supply (6 pins)
GND: pca20065_nrf9151 (50 pins), pca20065_sensors_and_leds (39 pins), pca20065_nrf5340 (43 pins), pca20065_interface (35 pins), pca20065_switch_fsa (C55.2 U12.6), pca20065_switch_nx (C34.1 U16.6), pca20065_power_supply (56 pins), pca20065_rf_front-end (15 pins), pca20065_nrf7002 (36 pins)
VBAT_nRF70: pca20065_interface (P9.2), pca20065_power_supply (TP13.1 U2.A1), pca20065_nrf7002 (8 pins)
VBUS: pca20065_interface (C44.2 FB2.2), pca20065_power_supply (C46.2 U11.21)
VBUSOUT: pca20065_nrf5340 (R10.1), pca20065_power_supply (C50.2 U11.22)
VDD_ACC: pca20065_sensors_and_leds (R26.1), pca20065_power_supply (ST7.2)
VDD_BMI270: pca20065_sensors_and_leds (SB4.1), pca20065_power_supply (ST1.2)
VDD_BMM350: pca20065_sensors_and_leds (SB10.1), pca20065_power_supply (ST4.2)
VDD_ENV: pca20065_sensors_and_leds (SB5.1), pca20065_power_supply (ST5.2)
VDD_EXP_BRD: pca20065_interface (C76.2 P1.2 R5.1 U24.B2), pca20065_power_supply (U14.A1)
VDD_LED: pca20065_sensors_and_leds (LED1.4 LED2.4), pca20065_power_supply (ST2.2)
VDD_MEM: pca20065_sensors_and_leds (C37.2 R43.2 R50.2 U7.C3), pca20065_power_supply (ST9.2)
VDD_nRF53: pca20065_nrf5340 (18 pins), pca20065_interface (P9.4), pca20065_power_supply (TP2.1 U3.A1)
VDD_nRF91: pca20065_nrf9151 (C1.1 C2.1 C3.1 FB1.1), pca20065_interface (P9.11), pca20065_power_supply (TP3.1 U4.A1)
VDD_nRF91_RES: pca20065_interface (P9.12), pca20065_power_supply (R24.1 U4.A2)
VDD_RF_FE_3V3: pca20065_nrf9151 (C32.2 C33.2 U9.3), pca20065_power_supply (R56.1 TP8.1 U13.A1)
VDD_RF_FE_SR: pca20065_power_supply (R25.1 TP11.1 U5.A1), pca20065_rf_front-end (R62.1 U22.4)
VOUT_BUCK3: pca20065_interface (P9.1), pca20065_power_supply (5 pins)
VSYS: pca20065_interface (Q6.4), pca20065_power_supply (C98.2 FB5.2 LED3.4 SW1.6)
2.4G_SW_CTRL: pca20065_nrf5340 (U6.H10), pca20065_rf_front-end (Q5.1), pca20065_nrf7002 (R33.2 U21.44)
4FF_1V8: pca20065_interface (C54.1 D3.5 J4.C1), pca20065_switch_nx (U16.1)
4FF_CLK: pca20065_interface (D3.7), pca20065_switch_nx (U16.9)
4FF_DETECT: pca20065_interface (J4.DSW R49.1), pca20065_switch_nx (U16.2)
4FF_IO: pca20065_interface (D3.6), pca20065_switch_nx (U16.5)
4FF_RST: pca20065_interface (D3.8), pca20065_switch_nx (U16.13)
ADXL367_INT: pca20065_nrf9151 (M1.70), pca20065_sensors_and_leds (U20.5), pca20065_nrf5340 (U6.E3)
BMI270_CS: pca20065_nrf9151 (M1.69), pca20065_sensors_and_leds (U18.12), pca20065_nrf5340 (U6.C6)
BMI270_INT: pca20065_nrf9151 (M1.63), pca20065_sensors_and_leds (U18.4), pca20065_nrf5340 (U6.L7)
BMM350_INT: pca20065_nrf9151 (M1.64), pca20065_sensors_and_leds (U26.A1), pca20065_nrf5340 (U6.C8)
BUCKEN: pca20065_nrf9151 (M1.47), pca20065_nrf5340 (U6.J10), pca20065_nrf7002 (R61.1 U21.30)
CC1: pca20065_interface (J6.A5), pca20065_power_supply (U11.23)
CC2: pca20065_interface (J6.B5), pca20065_power_supply (U11.24)
COEX_GRANT: pca20065_nrf5340 (U6.K5), pca20065_nrf7002 (U21.43)
COEX_REQ: pca20065_nrf5340 (U6.K4), pca20065_nrf7002 (R58.1 U21.42)
COEX_STATUS: pca20065_nrf5340 (U6.H3), pca20065_nrf7002 (R59.1 U21.41)
EXP_BOARD.PIN1: pca20065_nrf9151 (M1.80 TP33.1), pca20065_interface (P9.8 SB9.1 U24.D2)
EXP_BOARD.PIN2: pca20065_nrf9151 (M1.79 TP32.1), pca20065_interface (P9.9 SB8.1 U24.D1)
FLASH_~{CS}: pca20065_nrf9151 (M1.72), pca20065_sensors_and_leds (U7.C4), pca20065_nrf5340 (U6.G11)
HOST_IRQ: pca20065_nrf9151 (M1.77), pca20065_nrf5340 (U6.F10), pca20065_nrf7002 (U21.46)
LTE_BLE_COEX: pca20065_nrf9151 (M1.54 TP22.1), pca20065_nrf5340 (U6.E4), pca20065_power_supply (R53.2 U13.B2)
MFF_1V8: pca20065_interface (C59.2 U15.8), pca20065_switch_nx (U16.15)
MFF_CLK: pca20065_interface (U15.6), pca20065_switch_nx (U16.7)
MFF_IO: pca20065_interface (U15.3), pca20065_switch_nx (U16.3)
MFF_RST: pca20065_interface (U15.7), pca20065_switch_nx (U16.11)
MISO: pca20065_nrf9151 (M1.75), pca20065_sensors_and_leds (TP6.1 U7.D4 U18.1), pca20065_nrf5340 (U6.J8), pca20065_nrf7002 (U21.38)
MOSI: pca20065_nrf9151 (M1.74), pca20065_sensors_and_leds (TP37.1 U7.F3 U18.14), pca20065_nrf5340 (U6.J9), pca20065_nrf7002 (U21.37)
NetCR1_2: pca20065_nrf5340 (CR1.2 F1.4), pca20065_rf_front-end (U22.1)
NetF2_3: pca20065_rf_front-end (F2.3), pca20065_nrf7002 (U21.7)
NetJ1_1: pca20065_nrf9151 (M1.35), pca20065_rf_front-end (J1.1)
NetM1_3: pca20065_nrf9151 (M1.3), pca20065_switch_fsa (U12.5 U12.7)
NetM1_4: pca20065_nrf9151 (M1.4), pca20065_switch_fsa (U12.1 U12.11)
NetM1_27: pca20065_nrf9151 (M1.27), pca20065_rf_front-end (R27.1)
NetM1_28: pca20065_nrf9151 (M1.28), pca20065_rf_front-end (R28.1)
NetM1_29: pca20065_nrf9151 (M1.29), pca20065_rf_front-end (R29.1)
NetM1_44: pca20065_nrf9151 (M1.44), pca20065_nrf5340 (U6.C10), pca20065_interface (SW3.2 TP36.1), pca20065_power_supply (U11.7)
NetM1_48: pca20065_nrf9151 (M1.48), pca20065_sensors_and_leds (Q3.1 R44.2)
NetM1_49: pca20065_nrf9151 (M1.49), pca20065_sensors_and_leds (Q4.5 R46.2)
NetM1_50: pca20065_nrf9151 (M1.50), pca20065_sensors_and_leds (Q4.2 R45.2)
NetM1_59: pca20065_nrf9151 (M1.59), pca20065_power_supply (U14.B2)
NetP9_10: pca20065_interface (P9.10 TP1.1), pca20065_power_supply (R3.1 U2.B2 U3.B2 U4.B2)
NetQ1_1: pca20065_sensors_and_leds (Q1.1 R41.2), pca20065_nrf5340 (U6.J2)
NetQ2_2: pca20065_sensors_and_leds (Q2.2 R38.2), pca20065_nrf5340 (U6.K9)
NetQ2_5: pca20065_sensors_and_leds (Q2.5 R42.2), pca20065_nrf5340 (U6.L9)
NetQ6_6: pca20065_nrf5340 (SB7.2), pca20065_interface (Q6.6 TP35.1)
NetQ13_2: pca20065_nrf9151 (Q13.2 Q13.5 R107.1 R108.1), pca20065_nrf5340 (R16.2), pca20065_interface (U1.5)
NetR4_2: pca20065_nrf5340 (R4.2), pca20065_switch_fsa (U12.8)
NetR6_2: pca20065_nrf5340 (R6.2), pca20065_switch_fsa (U12.12)
NetR17_1: pca20065_interface (R17.1 R32.2), pca20065_switch_fsa (U12.10)
NetR18_2: pca20065_interface (R18.2 TP28.1 U1.4), pca20065_switch_fsa (U12.2)
NetSB6_2: pca20065_nrf9151 (SB6.2), pca20065_nrf5340 (TP5.1 U6.G2), pca20065_interface (U1.2)
NetU6_F1: pca20065_nrf5340 (U6.F1), pca20065_switch_fsa (U12.15)
NetU6_F2: pca20065_nrf5340 (U6.F2), pca20065_switch_fsa (U12.3)
NetU9_5: pca20065_nrf9151 (U9.5), pca20065_rf_front-end (Z23.1)
NetU21_9: pca20065_rf_front-end (U22.3), pca20065_nrf7002 (U21.9)
nPM1300_INT: pca20065_nrf9151 (M1.58), pca20065_power_supply (U11.10)
P0.08/TRACEDATA3: pca20065_nrf9151 (M1.12), pca20065_nrf5340 (U6.E10), pca20065_interface (P9.15)
P0.09/TRACEDATA2: pca20065_nrf9151 (M1.11), pca20065_nrf5340 (U6.D10), pca20065_interface (P9.16)
P0.10/TRACEDATA1: pca20065_nrf9151 (M1.8), pca20065_nrf5340 (U6.C5), pca20065_interface (P9.17)
P0.11/TRACEDATA0: pca20065_nrf9151 (M1.6), pca20065_nrf5340 (U6.C4), pca20065_interface (P9.18)
P0.12/TRACECLK: pca20065_nrf9151 (M1.5), pca20065_interface (P9.19)
QSPI_CLK: pca20065_nrf9151 (M1.73), pca20065_sensors_and_leds (TP38.1 U7.E3 U18.13), pca20065_nrf5340 (U6.L12), pca20065_nrf7002 (U21.35)
QSPI_SS: pca20065_nrf9151 (M1.78), pca20065_nrf5340 (U6.J7), pca20065_nrf7002 (U21.36)
RFFE_BLE_WIFI_ENABLE: pca20065_nrf5340 (U6.K7), pca20065_power_supply (U5.B2 U11.8)
SCL: pca20065_nrf9151 (M1.67), pca20065_sensors_and_leds (5 pins), pca20065_nrf5340 (U6.J11), pca20065_interface (SB8.2), pca20065_power_supply (U11.14 U25.E3)
SDA: pca20065_nrf9151 (M1.68), pca20065_sensors_and_leds (5 pins), pca20065_nrf5340 (U6.K12), pca20065_interface (SB9.2), pca20065_power_supply (U11.13 U25.E2)
SHPHLD: pca20065_interface (Q6.5 SW4.1), pca20065_power_supply (U11.15)
SIM.1V8: pca20065_nrf9151 (M1.19), pca20065_interface (R49.2), pca20065_switch_nx (C34.2 U16.14 U16.16)
SIM.CLK: pca20065_nrf9151 (M1.18), pca20065_switch_nx (U16.8)
SIM.IO: pca20065_nrf9151 (M1.17), pca20065_switch_nx (U16.4)
SIM.RST: pca20065_nrf9151 (M1.16), pca20065_switch_nx (U16.12)
SWDCLK: pca20065_interface (P8.4 P9.6 TP27.1), pca20065_switch_fsa (U12.4)
SWDIO: pca20065_interface (P8.2 P9.5 TP29.1), pca20065_switch_fsa (U12.16)
USB.D_N: pca20065_nrf5340 (U6.A11), pca20065_interface (C99.1 R31.1)
USB.D_P: pca20065_nrf5340 (U6.A12), pca20065_interface (C100.1 R34.1)
VCOM0.RXD: pca20065_nrf9151 (M1.57), pca20065_nrf5340 (U6.K3)
VCOM0.TXD: pca20065_nrf9151 (M1.56), pca20065_nrf5340 (U6.E2)
VCOM1.RXD: pca20065_nrf9151 (M1.62), pca20065_nrf5340 (U6.J3)
VCOM1.TXD: pca20065_nrf9151 (M1.61), pca20065_nrf5340 (U6.F3)
VDDIO_CTRL: pca20065_nrf9151 (M1.45), pca20065_nrf5340 (U6.G10), pca20065_nrf7002 (U10.B2)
